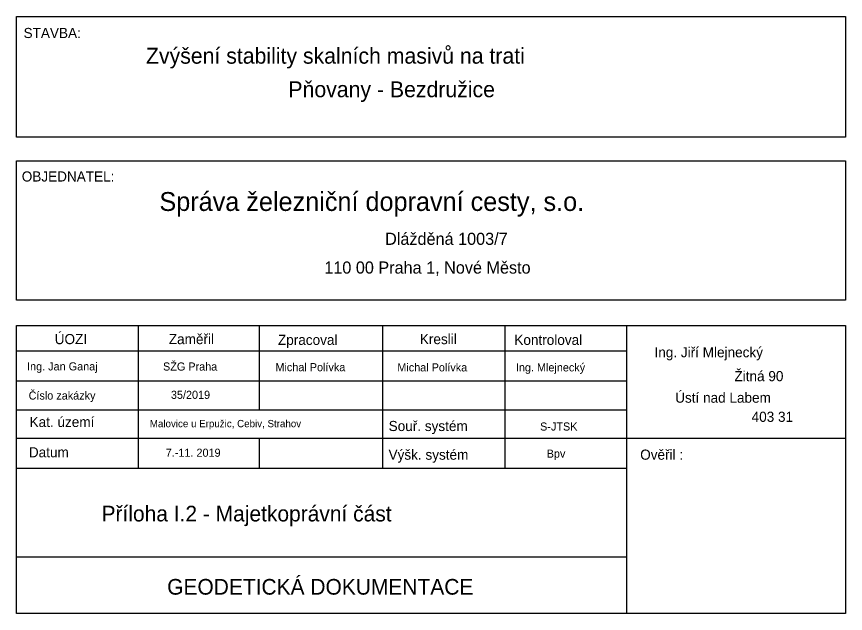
# Model space of a CAD drawing. Extents: x -879530 to -879371, y -1019242 to -1019127.
import ezdxf

# ---------------------------------------------------------------- set-up
doc = ezdxf.new("R2010")
doc.units = 0
doc.layers.add('LEGENDA', color=7, linetype='Continuous')
doc.layers.add('tabulka', color=7, linetype='Continuous')

msp = doc.modelspace()

# ---------------------------------------------------------------- linework, layer by layer
at = {"layer": 'tabulka'}
for p, q in [((-879530.09, -1019186.45), (-879371.44, -1019186.45)), ((-879506.8, -1019186.45), (-879506.8, -1019213.77)), ((-879483.66, -1019186.45), (-879483.66, -1019202.65)), ((-879460.06, -1019186.45), (-879460.06, -1019213.77)), ((-879436.61, -1019186.45), (-879436.61, -1019213.77)), ((-879413.31, -1019241.58), (-879413.31, -1019186.45)), ((-879530.09, -1019191.36), (-879413.31, -1019191.36)), ((-879530.09, -1019197.07), (-879413.31, -1019197.07)), ((-879530.09, -1019202.65), (-879413.31, -1019202.65)), ((-879530.09, -1019208.07), (-879371.44, -1019208.07)), ((-879483.66, -1019208.07), (-879483.66, -1019213.77)), ((-879530.09, -1019213.77), (-879413.31, -1019213.77)), ((-879530.09, -1019230.76), (-879413.31, -1019230.76))]:
    msp.add_line(p, q, dxfattribs=at)
for points in [[(-879530.09, -1019127.36), (-879371.44, -1019127.36), (-879371.44, -1019150.43), (-879530.09, -1019150.43)], [(-879530.09, -1019154.95), (-879371.44, -1019154.95), (-879371.44, -1019181.64), (-879530.09, -1019181.64)]]:
    msp.add_lwpolyline(points, close=True, dxfattribs=at)
msp.add_lwpolyline([(-879371.44, -1019186.45), (-879371.44, -1019241.58), (-879530.09, -1019241.58), (-879530.09, -1019186.45)], dxfattribs=at)

# ---------------------------------------------------------------- texts
at = {"layer": 'LEGENDA'}
for s, p in [('Zvýšení stability skalních masivů na trati', (-879505.32, -1019136.38)), ('Pňovany - Bezdružice', (-879478.06, -1019142.8))]:
    msp.add_text(s, height=3.04, dxfattribs=at).set_placement(p)
at = {"layer": 'tabulka'}
for s, height, p in [('STAVBA:', 1.94, (-879528.75, -1019131.47)), ('OBJEDNATEL:', 1.94, (-879529.1, -1019158.93)), ('Správa železniční dopravní cesty, s.o.', 3.61, (-879502.75, -1019164.56)), ('Dlážděná 1003/7', 2.32, (-879459.55, -1019171.05)), ('110 00 Praha 1, Nové Město', 2.32, (-879471.19, -1019176.55)), ('ÚOZI', 1.94, (-879522.79, -1019190.05)), ('Zaměřil', 1.94, (-879500.95, -1019190.05)), ('Zpracoval', 1.94, (-879480.06, -1019190.2)), ('Kreslil', 1.94, (-879452.9, -1019190.05)), ('Kontroloval', 1.94, (-879434.81, -1019190.2)), ('Ing. Jiří Mlejnecký', 1.94, (-879407.98, -1019192.57)), ('Ing. Jan Ganaj', 1.552, (-879528.08, -1019195.08)), ('SŽG Praha', 1.552, (-879502.06, -1019195.11)), ('Michal Polívka', 1.552, (-879480.54, -1019195.23)), ('Michal Polívka', 1.552, (-879457.21, -1019195.27)), ('Ing. Mlejnecký', 1.552, (-879434.52, -1019195.27)), ('Žitná 90', 1.94, (-879392.68, -1019197.14)), ('Číslo zakázky', 1.552, (-879527.79, -1019200.66)), ('35/2019', 1.552, (-879500.55, -1019200.52)), ('Ústí nad Labem', 1.94, (-879404.02, -1019201.26)), ('403 31', 1.94, (-879389.39, -1019204.92)), ('Kat. území', 1.94, (-879527.6, -1019205.91)), ('Malovice u Erpužic, Cebiv, Strahov', 1.3968, (-879504.59, -1019205.95)), ('Souř. systém', 1.94, (-879458.87, -1019206.68)), ('S-JTSK', 1.552, (-879429.88, -1019206.59)), ('Datum', 1.94, (-879527.74, -1019211.71)), ('7.-11. 2019', 1.552, (-879501.54, -1019211.6)), ('Výšk. systém', 1.94, (-879458.89, -1019212.17)), ('Bpv', 1.552, (-879428.62, -1019211.78)), ('Ověřil :', 1.94, (-879410.72, -1019212.17)), ('Příloha I.2 - Majetkoprávní část', 3, (-879513.83, -1019223.98)), ('GEODETICKÁ DOKUMENTACE ', 3, (-879501.27, -1019237.99))]:
    msp.add_text(s, height=height, dxfattribs=at).set_placement(p)

doc.saveas('drawing.dxf')
